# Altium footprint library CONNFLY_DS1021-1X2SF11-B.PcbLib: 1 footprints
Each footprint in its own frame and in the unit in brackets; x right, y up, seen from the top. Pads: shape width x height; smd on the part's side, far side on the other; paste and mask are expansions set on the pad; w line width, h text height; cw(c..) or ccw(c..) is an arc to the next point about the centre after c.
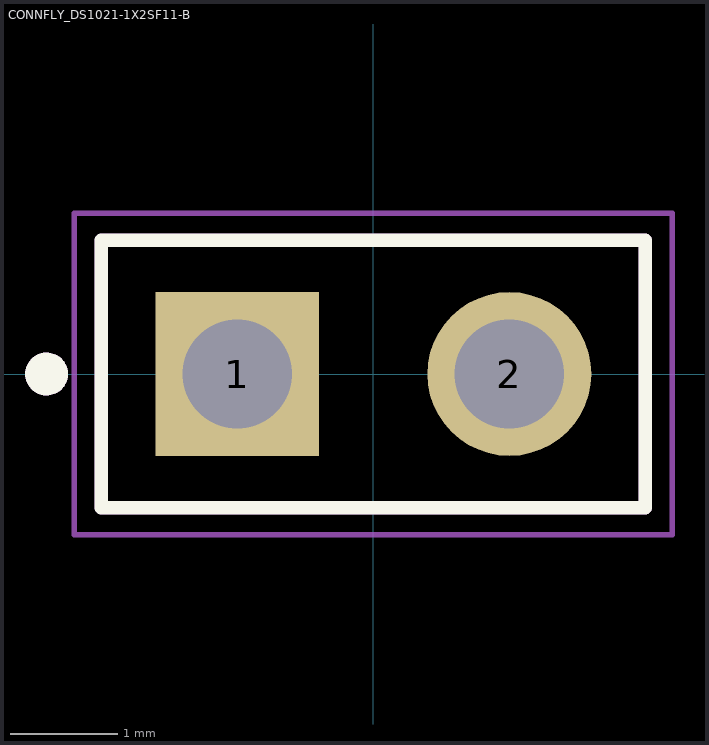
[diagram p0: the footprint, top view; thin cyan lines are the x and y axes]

## CONNFLY_DS1021-1X2SF11-B [mm]
pads (2):
  rect 1.53x1.53 / inner round 1.53 / far side rect 1.53x1.53 hole 1.02 mask+0.102: 1(-1.27,0)
  round 1.53 hole 1.02 mask+0.102: 2(1.27,0)
Top Overlay:
  circle w0.2: c-3.05,0 r0.1
  lines w0.127: -2.54,-1.25 -2.54,1.25 2.54,1.25 2.54,-1.25 -2.54,-1.25
Assembly Top:
  circle w0.2: c-3.05,0 r0.1
  lines w0.127: -2.54,-1.25 -2.54,1.25 2.54,1.25 2.54,-1.25 -2.54,-1.25
Courtyard Top:
  lines w0.05: -2.79,-1.5 -2.79,1.5 2.79,1.5 2.79,-1.5 -2.79,-1.5
3D body "step_temp.STEP": height 8.6, standoff -3, extent -2.54,-1.25 2.54,1.25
